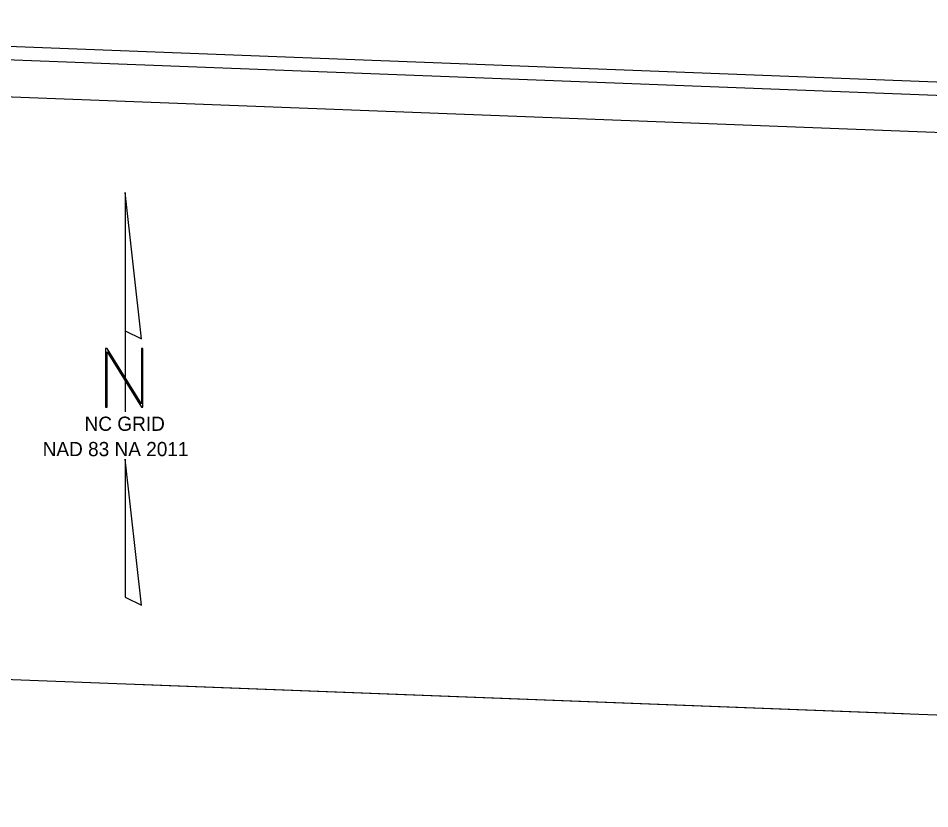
# Model space of a CAD drawing. Extents: x 2097521 to 2097987, y 686521 to 687299.
# Drawn here: x 2097648.4 to 2097771.5, y 687104.4 to 687211.1 of the extents above; entities that cross this region are included whole.
import ezdxf

# ---------------------------------------------------------------- set-up
doc = ezdxf.new("R2010")
doc.units = 0
for name, color, linetype in [('Default', 7, 'Continuous'), ('Matchline', 7, 'Continuous'), ('Sheet Layout Plan Border', 7, 'Continuous'), ('Sheet Plot Border Inside CELL', 7, 'Continuous'), ('Sheet Plot Border Outside CELL', 7, 'Continuous'), ('Sheet Profile CELL', 7, 'Continuous')]:
    doc.layers.add(name, color=color, linetype=linetype)

msp = doc.modelspace()

# ---------------------------------------------------------------- linework, layer by layer
at = {"layer": 'Default'}
msp.add_line((2097662.87, 687159.66), (2097662.87, 687159.66), dxfattribs=at)
for points in [[(2097662.82, 687187.6), (2097662.82, 687168.93), (2097665.02, 687167.83)], [(2097660.19, 687158.62), (2097660.41, 687158.62), (2097660.41, 687166.08), (2097665.02, 687158.62), (2097665.24, 687158.62), (2097665.24, 687166.52), (2097665.02, 687166.52), (2097665.02, 687159.06), (2097660.41, 687166.52), (2097660.19, 687166.52)], [(2097662.82, 687132.93), (2097665.02, 687131.84), (2097662.82, 687151.59)]]:
    msp.add_lwpolyline(points, close=True, dxfattribs=at)
msp.add_lwpolyline([(2097662.82, 687168.93), (2097662.82, 687157.96)], dxfattribs=at)
at = {"layer": 'Matchline'}
msp.add_line((2097664.27, 687121.19), (2097767.89, 687117.21), dxfattribs=at)
at = {"layer": 'Sheet Layout Plan Border'}
msp.add_lwpolyline([(2097534.78, 686624.29), (2097553.94, 687123.99), (2097611.01, 687121.8), (2097611.07, 687123.23), (2097798.3, 687116.05), (2097794.51, 687017.17), (2097779.16, 686617.13)], close=True, dxfattribs=at)
at = {"layer": 'Sheet Plot Border Inside CELL'}
msp.add_lwpolyline([(2097952.36, 686526.7), (2097977.91, 687192.81), (2097556.18, 687208.99), (2097530.63, 686542.88)], close=True, dxfattribs=at)
at = {"layer": 'Sheet Plot Border Outside CELL'}
msp.add_lwpolyline([(2097961.14, 686521.16), (2097986.95, 687194.27), (2097547.28, 687211.13), (2097521.46, 686538.02)], close=True, dxfattribs=at)
at = {"layer": 'Sheet Profile CELL'}
msp.add_lwpolyline([(2097557.01, 687203.95), (2097534.01, 686604.39), (2097953.71, 686588.3), (2097976.7, 687187.85)], close=True, dxfattribs=at)

# ---------------------------------------------------------------- texts
at = {"layer": 'Default'}
for s, p in [('NC GRID', (2097657.35, 687155.4)), ('NAD 83 NA 2011', (2097651.69, 687151.98))]:
    msp.add_text(s, height=1.92, dxfattribs=at).set_placement(p)

doc.saveas('drawing.dxf')
